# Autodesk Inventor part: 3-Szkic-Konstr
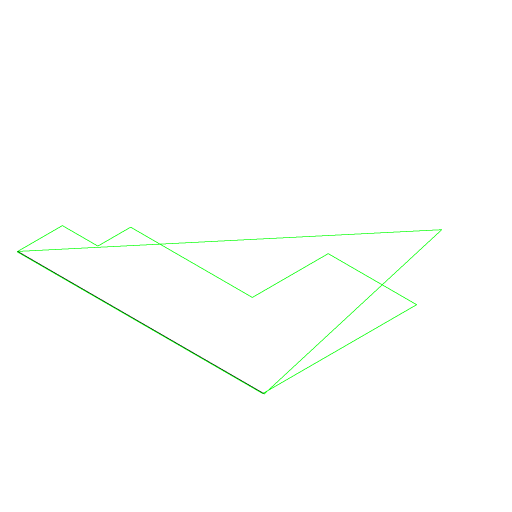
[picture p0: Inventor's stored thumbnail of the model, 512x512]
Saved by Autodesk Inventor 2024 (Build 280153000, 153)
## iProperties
Company: ATC
Shininess: 20.0
Length Units: 11269
Angle Units: 11279
Time Units: 11290
Mass Units: 11283
Length Display Precision: 3
Angle Display Precision: 2
Compacted: True
Created: 2023-03
Part Number: 3-Szkic-Konstr
Document SubType Name: Modeling
Designer: Andrzej Jaskulski
Material: Kurs-AJ
Density: 1 g/cm^3
Appearance: Kurs-AJ
Checked By: A.J.
Engr Approved By: Andrzej Jaskulski
Mfg Approved By: Andrzej Jaskulski
Authority: A.J.
Density: 0.0
Volumn: 0.0
Area: 0.0
PropertySet Name: Model Information
Control State: 0
Master: False
Checked Out: False
Title: A.J.: Kurs R2024-MEP
Author: Andrzej Jaskulski
Revision Number: 1/24
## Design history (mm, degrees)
sketch "Schody"
  geometry: L1 (0.405, -2.709)-(55.123, -2.709); L2 (55.123, -2.709)-(55.123, 31.581); L3 (55.123, 31.581)-(35.424, 31.581); L4 (35.424, 31.581)-(35.424, 14.679); L5 (35.424, 14.679)-(8.308, 14.679); L6 (8.308, 14.679)-(8.308, 7.383); L7 (8.308, 7.383)-(0.405, 7.383); L8 (0.405, 7.383)-(0.405, -2.709)
  constraints: 16 end point, 4 parallel, 3 perpendicular, 1 horizontal
sketch "Trójkąt"
  geometry: L1 (0.405, -2.588)-(55.366, -2.588); L2 (55.366, -2.588)-(43.45, 48.847); L3 (43.45, 48.847)-(0.405, -2.588)
  constraints: 6 end point, 1 horizontal, 1 other
node "Korpusy bryłowe"
node "Korpusy powierzchniowe"
